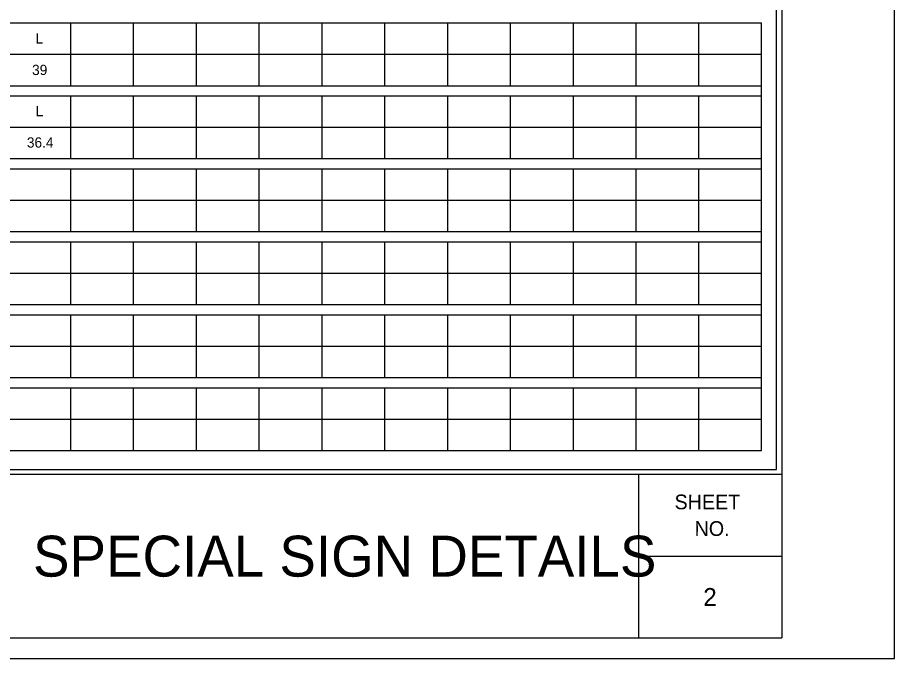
# Model space of a CAD drawing. Extents: x 17890628 to 17890844, y 17897508 to 17897992.
# Drawn here: x 17890806.91 to 17890844.26, y 17897507.74 to 17897535.03 of the extents above; entities that cross this region are included whole.
import ezdxf

# ---------------------------------------------------------------- set-up
doc = ezdxf.new("R2010")
doc.units = 0
for name, color, linetype in [('GSSign', 7, 'Continuous'), ('PlotBorder_dp', 7, 'Continuous'), ('SheetBorder_dp', 7, 'Continuous'), ('SheetLinesMisc2_dp', 7, 'Continuous'), ('TextMisc', 7, 'Continuous'), ('TextShtNo', 7, 'Continuous')]:
    doc.layers.add(name, color=color, linetype=linetype)

msp = doc.modelspace()

# ---------------------------------------------------------------- linework, layer by layer
at = {"layer": 'PlotBorder_dp'}
msp.add_lwpolyline([(17890700.471, 17897507.741), (17890844.259, 17897507.741), (17890844.259, 17897600.116), (17890700.471, 17897600.116)], close=True, dxfattribs=at)
at = {"layer": 'SheetBorder_dp'}
for p, q in [((17890839.466, 17897599.245), (17890839.466, 17897508.613)), ((17890705.263, 17897515.585), (17890839.466, 17897515.585)), ((17890833.367, 17897508.612), (17890833.367, 17897515.584)), ((17890833.366, 17897512.099), (17890839.466, 17897512.099)), ((17890705.263, 17897508.613), (17890839.466, 17897508.613))]:
    msp.add_line(p, q, dxfattribs=at)
at = {"layer": 'SheetLinesMisc2_dp'}
for p, q in [((17890839.233, 17897515.791), (17890839.233, 17897599.038)), ((17890772.824, 17897534.804), (17890838.594, 17897534.804)), ((17890809.164, 17897534.804), (17890809.164, 17897532.131)), ((17890811.839, 17897534.804), (17890811.839, 17897532.131)), ((17890814.514, 17897534.804), (17890814.514, 17897532.131)), ((17890817.19, 17897534.804), (17890817.19, 17897532.131)), ((17890819.866, 17897534.804), (17890819.866, 17897532.131)), ((17890822.541, 17897534.804), (17890822.541, 17897532.131)), ((17890825.216, 17897534.804), (17890825.216, 17897532.131)), ((17890827.892, 17897534.804), (17890827.892, 17897532.131)), ((17890830.568, 17897534.804), (17890830.568, 17897532.131)), ((17890833.243, 17897534.804), (17890833.243, 17897532.131)), ((17890835.919, 17897534.804), (17890835.919, 17897532.131)), ((17890838.594, 17897516.593), (17890838.594, 17897534.804)), ((17890772.824, 17897533.468), (17890838.594, 17897533.468)), ((17890772.824, 17897532.131), (17890838.594, 17897532.131)), ((17890772.824, 17897531.696), (17890838.594, 17897531.696)), ((17890809.164, 17897531.696), (17890809.164, 17897529.023)), ((17890811.839, 17897531.696), (17890811.839, 17897529.023)), ((17890814.514, 17897531.696), (17890814.514, 17897529.023)), ((17890817.19, 17897531.696), (17890817.19, 17897529.023)), ((17890819.866, 17897531.696), (17890819.866, 17897529.023)), ((17890822.541, 17897531.696), (17890822.541, 17897529.023)), ((17890825.216, 17897531.696), (17890825.216, 17897529.023)), ((17890827.892, 17897531.696), (17890827.892, 17897529.023)), ((17890830.568, 17897531.696), (17890830.568, 17897529.023)), ((17890833.243, 17897531.696), (17890833.243, 17897529.023)), ((17890835.919, 17897531.696), (17890835.919, 17897529.023)), ((17890772.824, 17897530.359), (17890838.594, 17897530.359)), ((17890772.824, 17897529.023), (17890838.594, 17897529.023)), ((17890772.824, 17897528.588), (17890838.594, 17897528.588)), ((17890809.164, 17897528.588), (17890809.164, 17897525.916)), ((17890811.839, 17897528.588), (17890811.839, 17897525.916)), ((17890814.514, 17897528.588), (17890814.514, 17897525.916)), ((17890817.19, 17897528.588), (17890817.19, 17897525.916)), ((17890819.866, 17897528.588), (17890819.866, 17897525.916)), ((17890822.541, 17897528.588), (17890822.541, 17897525.916)), ((17890825.216, 17897528.588), (17890825.216, 17897525.916)), ((17890827.892, 17897528.588), (17890827.892, 17897525.916)), ((17890830.568, 17897528.588), (17890830.568, 17897525.916)), ((17890833.243, 17897528.588), (17890833.243, 17897525.916)), ((17890835.919, 17897528.588), (17890835.919, 17897525.916)), ((17890772.824, 17897527.252), (17890838.594, 17897527.252)), ((17890772.824, 17897525.916), (17890838.594, 17897525.916)), ((17890772.824, 17897525.48), (17890838.594, 17897525.48)), ((17890809.164, 17897525.48), (17890809.164, 17897522.808)), ((17890811.839, 17897525.48), (17890811.839, 17897522.808)), ((17890814.514, 17897525.48), (17890814.514, 17897522.808)), ((17890817.19, 17897525.48), (17890817.19, 17897522.808)), ((17890819.866, 17897525.48), (17890819.866, 17897522.808)), ((17890822.541, 17897525.48), (17890822.541, 17897522.808)), ((17890825.216, 17897525.48), (17890825.216, 17897522.808)), ((17890827.892, 17897525.48), (17890827.892, 17897522.808)), ((17890830.568, 17897525.48), (17890830.568, 17897522.808)), ((17890833.243, 17897525.48), (17890833.243, 17897522.808)), ((17890835.919, 17897525.48), (17890835.919, 17897522.808)), ((17890772.824, 17897524.145), (17890838.594, 17897524.145)), ((17890772.824, 17897522.808), (17890838.594, 17897522.808)), ((17890772.824, 17897522.372), (17890838.594, 17897522.372)), ((17890809.164, 17897522.372), (17890809.164, 17897519.7)), ((17890811.839, 17897522.372), (17890811.839, 17897519.7)), ((17890814.514, 17897522.372), (17890814.514, 17897519.7)), ((17890817.19, 17897522.372), (17890817.19, 17897519.7)), ((17890819.866, 17897522.372), (17890819.866, 17897519.7)), ((17890822.541, 17897522.372), (17890822.541, 17897519.7)), ((17890825.216, 17897522.372), (17890825.216, 17897519.7)), ((17890827.892, 17897522.372), (17890827.892, 17897519.7)), ((17890830.568, 17897522.372), (17890830.568, 17897519.7)), ((17890833.243, 17897522.372), (17890833.243, 17897519.7)), ((17890835.919, 17897522.372), (17890835.919, 17897519.7)), ((17890772.824, 17897521.036), (17890838.594, 17897521.036)), ((17890772.824, 17897519.7), (17890838.594, 17897519.7)), ((17890772.824, 17897519.264), (17890838.594, 17897519.264)), ((17890809.164, 17897519.264), (17890809.164, 17897516.593)), ((17890811.839, 17897519.264), (17890811.839, 17897516.593)), ((17890814.514, 17897519.264), (17890814.514, 17897516.593)), ((17890817.19, 17897519.264), (17890817.19, 17897516.593)), ((17890819.866, 17897519.264), (17890819.866, 17897516.593)), ((17890822.541, 17897519.264), (17890822.541, 17897516.593)), ((17890825.216, 17897519.264), (17890825.216, 17897516.593)), ((17890827.892, 17897519.264), (17890827.892, 17897516.593)), ((17890830.568, 17897519.264), (17890830.568, 17897516.593)), ((17890833.243, 17897519.264), (17890833.243, 17897516.593)), ((17890835.919, 17897519.264), (17890835.919, 17897516.593)), ((17890772.824, 17897517.928), (17890838.594, 17897517.928)), ((17890772.824, 17897516.593), (17890838.594, 17897516.593)), ((17890705.5, 17897515.791), (17890839.233, 17897515.791))]:
    msp.add_line(p, q, dxfattribs=at)

# ---------------------------------------------------------------- texts
at = {"layer": 'GSSign'}
for s, height, p in [('L', 0.436, (17890807.678, 17897533.921)), ('39', 0.4357, (17890807.528, 17897532.584)), ('L', 0.436, (17890807.682, 17897530.831)), ('36.4', 0.4357, (17890807.306, 17897529.495))]:
    msp.add_text(s, height=height, dxfattribs=at).set_placement(p)
at = {"layer": 'TextMisc'}
for s, p in [('SHEET', (17890834.892, 17897514.094)), ('NO.', (17890835.745, 17897512.961))]:
    msp.add_text(s, height=0.6274, rotation=359.8607, dxfattribs=at).set_placement(p)
msp.add_text('SPECIAL SIGN DETAILS', height=1.7429, dxfattribs=at).set_placement((17890807.568, 17897511.226))
at = {"layer": 'TextShtNo'}
msp.add_text('2', height=0.767, dxfattribs=at).set_placement((17890836.118, 17897509.972))

doc.saveas('drawing.dxf')
